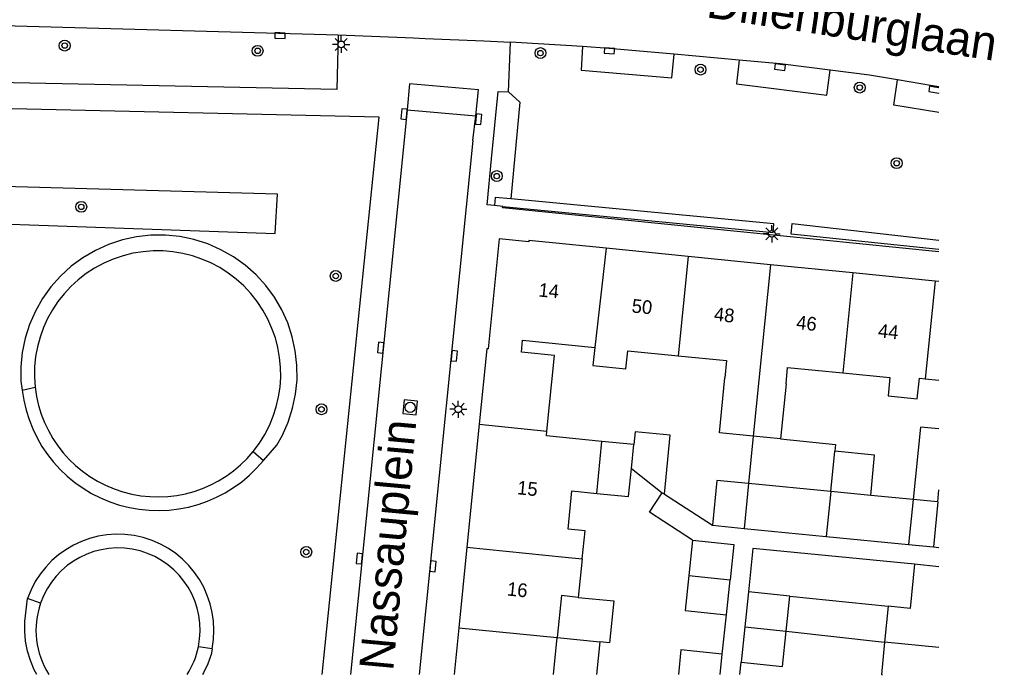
# Model space of a CAD drawing. Extents: x 132573 to 132944, y 398226 to 398676.
# Drawn here: x 132872.8 to 132944.2, y 398226.3 to 398274.2 of the extents above; entities that cross this region are included whole.
import ezdxf

# ---------------------------------------------------------------- set-up
doc = ezdxf.new("R2010")
doc.units = 0
for name, color, linetype in [('gg-afsc-erfafscheiding', 7, 'Continuous'), ('gg-anno-huisnummerreeks BGT', 7, 'Continuous'), ('gg-anno-openbare ruimte label', 7, 'Continuous'), ('gg-bbg-bijgebouw', 7, 'Continuous'), ('gg-bbg-gedigitaliseerde bebouwing', 7, 'Continuous'), ('gg-bbg-gedigitaliseerde bijgebouw', 7, 'Continuous'), ('gg-bbg-hoofdgebouw', 7, 'Continuous'), ('gg-bbg-luifel en loopbrug', 7, 'Continuous'), ('gg-bbg-tussenscheiding', 7, 'Continuous'), ('gg-knt-verharding', 7, 'Continuous'), ('gt-grn-groengrens', 7, 'Continuous'), ('gt-symb-boom', 7, 'Continuous'), ('gt-symb-kolk', 7, 'Continuous'), ('gt-symb-lichtmast', 7, 'Continuous'), ('gt-symb-rioolschacht', 7, 'Continuous')]:
    doc.layers.add(name, color=color, linetype=linetype)

msp = doc.modelspace()

# ---------------------------------------------------------------- linework, layer by layer
at = {"layer": 'gg-afsc-erfafscheiding'}
for p, q in [((132920.02, 398239.507), (132923.532, 398237.217)), ((132939.716, 398235.638), (132940.113, 398235.59)), ((132924.261, 398227.79), (132924.56, 398230.659)), ((132925.551, 398226.299), (132925.645, 398227.202))]:
    msp.add_line(p, q, dxfattribs=at)
for points in [[(132922.068, 398236.125), (132918.932, 398238.169), (132919.869, 398239.606)], [(132938.333, 398234.365), (132926.49, 398235.521), (132926.181, 398232.354)]]:
    msp.add_lwpolyline(points, dxfattribs=at)
at = {"layer": 'gg-bbg-bijgebouw'}
msp.add_line((132940.024, 398238.924), (132939.716, 398235.638), dxfattribs=at)
at = {"layer": 'gg-bbg-gedigitaliseerde bebouwing'}
for p, q in [((132911.426, 398244.114), (132911.98, 398249.64)), ((132933.08, 398248.376), (132936.533, 398248.038)), ((132928.922, 398247.568), (132928.515, 398243.538)), ((132938.682, 398247.991), (132939.12, 398247.945)), ((132939.12, 398247.945), (132940.113, 398247.842)), ((132928.515, 398243.538), (132926.529, 398243.732)), ((132914.005, 398234.769), (132913.72, 398231.945)), ((132940.113, 398234.188), (132938.333, 398234.365)), ((132936.404, 398231.29), (132936.142, 398228.67)), ((132911.908, 398226.299), (132912.178, 398228.999))]:
    msp.add_line(p, q, dxfattribs=at)
for points in [[(132909.551, 398249.885), (132909.637, 398250.761), (132914.92, 398250.241)], [(132914.92, 398250.241), (132914.791, 398248.918), (132917.207, 398248.682), (132917.335, 398249.993), (132921.04, 398249.631)], [(132921.04, 398249.631), (132924.572, 398249.286), (132924.447, 398248.005)], [(132928.922, 398247.568), (132929.04, 398248.772), (132933.08, 398248.376)], [(132926.529, 398243.732), (132924.054, 398243.974), (132924.447, 398248.005)], [(132936.533, 398248.038), (132936.394, 398246.7), (132938.525, 398246.478), (132938.682, 398247.991)], [(132915.45, 398243.355), (132911.391, 398243.762), (132911.426, 398244.114)], [(132912.973, 398236.938), (132913.252, 398239.73), (132915.069, 398239.548)], [(132914.005, 398234.769), (132914.211, 398236.813), (132912.973, 398236.938)], [(132938.333, 398234.365), (132938.009, 398231.13), (132936.404, 398231.29)], [(132913.72, 398231.945), (132912.485, 398232.069), (132912.178, 398228.999)], [(132936.142, 398228.67), (132935.907, 398226.307), (132935.99, 398226.299)]]:
    msp.add_lwpolyline(points, dxfattribs=at)
at = {"layer": 'gg-bbg-gedigitaliseerde bijgebouw'}
for p, q in [((132917.778, 398243.122), (132915.45, 398243.355)), ((132917.604, 398241.385), (132919.869, 398239.606)), ((132932.202, 398239.688), (132926.18, 398240.276)), ((132935.143, 398239.401), (132932.202, 398239.688)), ((132919.869, 398239.606), (132920.02, 398239.507)), ((132938.226, 398239.1), (132935.143, 398239.401)), ((132940.024, 398238.924), (132938.226, 398239.1)), ((132923.532, 398237.217), (132925.848, 398236.991)), ((132925.848, 398236.991), (132931.87, 398236.404)), ((132922.068, 398236.125), (132921.8, 398233.549)), ((132931.87, 398236.404), (132937.895, 398235.816)), ((132937.895, 398235.816), (132939.716, 398235.638)), ((132924.56, 398230.659), (132924.828, 398233.235)), ((132926.181, 398232.354), (132925.913, 398229.778)), ((132929.208, 398232.039), (132926.181, 398232.354)), ((132928.94, 398229.463), (132929.208, 398232.039)), ((132925.913, 398229.778), (132925.645, 398227.202))]:
    msp.add_line(p, q, dxfattribs=at)
for points in [[(132920.02, 398239.507), (132920.454, 398243.811), (132917.873, 398244.071), (132917.778, 398243.122)], [(132915.069, 398239.548), (132917.397, 398239.315), (132917.604, 398241.385)], [(132926.18, 398240.276), (132923.853, 398240.503), (132923.532, 398237.217)], [(132922.068, 398236.125), (132925.096, 398235.81), (132924.828, 398233.235)], [(132921.8, 398233.549), (132921.532, 398230.973), (132924.56, 398230.659)], [(132925.645, 398227.202), (132928.672, 398226.888), (132928.94, 398229.463)]]:
    msp.add_lwpolyline(points, dxfattribs=at)
at = {"layer": 'gg-bbg-hoofdgebouw'}
for p, q in [((132921.772, 398256.899), (132915.751, 398257.505)), ((132927.794, 398256.293), (132921.772, 398256.899)), ((132933.816, 398255.687), (132927.794, 398256.293)), ((132939.838, 398255.081), (132933.816, 398255.687)), ((132940.113, 398255.053), (132939.838, 398255.081)), ((132907.015, 398250.136), (132906.457, 398244.616)), ((132911.98, 398249.64), (132909.551, 398249.885)), ((132906.457, 398244.616), (132905.555, 398235.617)), ((132905.555, 398235.617), (132904.964, 398229.721)), ((132904.964, 398229.721), (132904.622, 398226.299))]:
    msp.add_line(p, q, dxfattribs=at)
for points in [[(132907.919, 398258.178), (132907.123, 398250.129), (132907.015, 398250.136)], [(132915.751, 398257.505), (132910.106, 398258.073), (132910.096, 398257.961), (132907.919, 398258.178)]]:
    msp.add_lwpolyline(points, dxfattribs=at)
at = {"layer": 'gg-bbg-luifel en loopbrug'}
for p, q in [((132926.529, 398243.732), (132926.18, 398240.276)), ((132932.202, 398239.688), (132932.501, 398242.646)), ((132940.024, 398238.924), (132940.113, 398239.806)), ((132929.208, 398232.039), (132936.404, 398231.29)), ((132912.178, 398228.999), (132915.284, 398228.688)), ((132928.94, 398229.463), (132936.142, 398228.67)), ((132915.284, 398228.688), (132915.045, 398226.299)), ((132924.106, 398226.299), (132924.261, 398227.79))]:
    msp.add_line(p, q, dxfattribs=at)
for points in [[(132940.113, 398244.276), (132938.762, 398244.408), (132938.226, 398239.1)], [(132928.515, 398243.538), (132932.551, 398243.144), (132932.501, 398242.646)], [(132935.143, 398239.401), (132935.392, 398242.359), (132932.501, 398242.646)], [(132913.72, 398231.945), (132916.317, 398231.685), (132916.01, 398228.616), (132915.284, 398228.688)], [(132924.261, 398227.79), (132921.233, 398228.093), (132921.046, 398226.299)]]:
    msp.add_lwpolyline(points, dxfattribs=at)
at = {"layer": 'gg-bbg-tussenscheiding'}
for p, q in [((132915.751, 398257.505), (132914.92, 398250.241)), ((132921.772, 398256.899), (132921.04, 398249.631)), ((132927.794, 398256.293), (132926.529, 398243.732)), ((132933.816, 398255.687), (132933.08, 398248.376)), ((132939.838, 398255.081), (132939.12, 398247.945)), ((132906.457, 398244.616), (132911.426, 398244.114)), ((132915.069, 398239.548), (132915.45, 398243.355)), ((132917.604, 398241.385), (132917.778, 398243.122)), ((132926.18, 398240.276), (132925.848, 398236.991)), ((132932.202, 398239.688), (132931.87, 398236.404)), ((132938.226, 398239.1), (132937.895, 398235.816)), ((132905.555, 398235.617), (132912.768, 398234.894)), ((132912.768, 398234.894), (132914.005, 398234.769)), ((132921.8, 398233.549), (132924.828, 398233.235)), ((132904.964, 398229.721), (132912.178, 398228.999)), ((132925.913, 398229.778), (132928.94, 398229.463)), ((132940.113, 398228.273), (132936.142, 398228.67))]:
    msp.add_line(p, q, dxfattribs=at)
at = {"layer": 'gg-knt-verharding'}
for p, q in [((132871.622, 398273.797), (132896.134, 398273.123)), ((132896.134, 398273.123), (132896.036, 398269.121)), ((132896.134, 398273.123), (132901.659, 398272.888)), ((132901.659, 398272.888), (132902.514, 398272.852)), ((132902.514, 398272.852), (132906.8, 398272.67)), ((132906.8, 398272.67), (132908.758, 398272.587)), ((132908.606, 398268.934), (132908.758, 398272.587)), ((132914.019, 398272.258), (132908.758, 398272.587)), ((132925.496, 398271.263), (132920.725, 398271.691)), ((132896.036, 398269.121), (132864.837, 398269.763)), ((132901.358, 398269.527), (132901.188, 398267.636)), ((132906.411, 398269.08), (132901.358, 398269.527)), ((132906.206, 398267.192), (132906.411, 398269.08)), ((132899.13, 398267.08), (132864.794, 398267.865)), ((132901.188, 398267.636), (132901.031, 398265.885)), ((132901.188, 398267.636), (132906.206, 398267.192)), ((132894.97, 398226.299), (132899.13, 398267.08)), ((132906.009, 398265.377), (132906.206, 398267.192)), ((132901.031, 398265.885), (132897.043, 398226.299)), ((132906.009, 398265.377), (132902.079, 398226.299)), ((132907.04, 398260.67), (132907.357, 398264.044)), ((132907.577, 398260.618), (132907.04, 398260.67)), ((132908.183, 398260.558), (132907.577, 398260.618)), ((132873.012, 398247.111), (132873.961, 398247.319)), ((132889.922, 398242.613), (132890.665, 398241.956)), ((132874.363, 398231.518), (132873.403, 398231.866)), ((132886.908, 398228.188), (132885.91, 398228.324))]:
    msp.add_line(p, q, dxfattribs=at)
for points in [[(132914.019, 398272.258), (132913.93, 398270.519), (132920.567, 398269.978), (132920.725, 398271.691)], [(132920.725, 398271.691), (132915.962, 398272.119), (132914.019, 398272.258)], [(132925.496, 398271.263), (132925.286, 398269.53), (132931.901, 398268.697), (132932.15, 398270.528)], [(132932.15, 398270.528), (132928.487, 398270.994), (132925.496, 398271.263)], [(132937.083, 398269.815), (132935.03, 398270.161), (132932.15, 398270.528)], [(132940.113, 398267.425), (132936.811, 398267.975), (132937.083, 398269.815)], [(132940.113, 398269.297), (132939.65, 398269.383), (132937.083, 398269.815)], [(132907.357, 398264.044), (132907.864, 398268.957), (132908.606, 398268.934)], [(132940.113, 398257.242), (132908.173, 398260.447), (132908.183, 398260.558)]]:
    msp.add_lwpolyline(points, dxfattribs=at)
for centre, radius, start, end in [((132882.922, 398248.293), 9.014, 320.94197, 186.20239), ((132882.936, 398248.293), 9.995, 186.79431, 320.64815), ((132882.933, 398248.329), 9.029, 186.42238, 320.72198), ((132880.025, 398229.547), 7.016, 348.83227, 160.69842), ((132880.036, 398229.556), 6.002, 348.15335, 160.92284), ((132880.027, 398229.526), 6.004, 160.62684, 212.51609), ((132880.027, 398229.526), 6.004, 327.48391, 348.44935)]:
    msp.add_arc(centre, radius, start, end, dxfattribs=at)
at = {"layer": 'gt-grn-groengrens'}
msp.add_line((132940.113, 398257.4), (132929.295, 398258.516), dxfattribs=at)
for points in [[(132908.606, 398268.934), (132909.439, 398268.187), (132908.787, 398261.111)], [(132854.2, 398262.504), (132854.161, 398259.901), (132891.539, 398258.578), (132891.698, 398261.456), (132854.2, 398262.504)], [(132908.787, 398261.111), (132907.636, 398261.22), (132907.577, 398260.618)], [(132908.183, 398260.558), (132927.971, 398258.653), (132928.037, 398259.294), (132908.787, 398261.111)], [(132929.295, 398258.516), (132929.378, 398259.318), (132940.113, 398258.087)], [(132890.665, 398241.956), (132891.663, 398243.085), (132892.062, 398243.806), (132892.487, 398244.776), (132892.809, 398245.785), (132893.023, 398246.822), (132893.128, 398247.876), (132893.122, 398248.935), (132893.005, 398249.988), (132892.779, 398251.023), (132892.446, 398252.028), (132892.009, 398252.993), (132891.474, 398253.908), (132890.847, 398254.761), (132890.133, 398255.544), (132889.342, 398256.248), (132888.482, 398256.866), (132887.561, 398257.39), (132886.591, 398257.815), (132885.582, 398258.137), (132884.545, 398258.351), (132883.491, 398258.456), (132882.432, 398258.449), (132881.379, 398258.333), (132880.344, 398258.106), (132879.339, 398257.773), (132878.374, 398257.337), (132877.459, 398256.802), (132876.606, 398256.174), (132875.823, 398255.461), (132875.119, 398254.67), (132874.501, 398253.81), (132873.977, 398252.889), (132873.552, 398251.919), (132873.23, 398250.91), (132873.016, 398249.873), (132872.911, 398248.819), (132872.918, 398247.759), (132873.012, 398247.111)], [(132874.084, 398226.299), (132873.893, 398226.645), (132873.609, 398227.316), (132873.397, 398228.013), (132873.259, 398228.728), (132873.197, 398229.453), (132873.211, 398230.182), (132873.403, 398231.866)], [(132886.908, 398228.188), (132886.835, 398227.758), (132886.597, 398227.069), (132886.288, 398226.41), (132886.221, 398226.299)]]:
    msp.add_lwpolyline(points, dxfattribs=at)
at = {"layer": 'gt-symb-boom'}
for centre, radius in [((132876.122, 398272.33), 0.4), ((132876.122, 398272.33), 0.2), ((132890.246, 398271.945), 0.4), ((132890.246, 398271.945), 0.2), ((132910.949, 398271.78), 0.4), ((132910.949, 398271.78), 0.2), ((132922.663, 398270.57), 0.4), ((132922.663, 398270.57), 0.2), ((132934.319, 398269.257), 0.4), ((132934.319, 398269.257), 0.2), ((132937.024, 398263.721), 0.4), ((132937.024, 398263.721), 0.2), ((132907.753, 398262.777), 0.4), ((132907.753, 398262.777), 0.2), ((132877.334, 398260.525), 0.4), ((132877.334, 398260.525), 0.2), ((132895.965, 398255.468), 0.4), ((132895.965, 398255.468), 0.2), ((132894.92, 398245.709), 0.4), ((132894.92, 398245.709), 0.2), ((132893.805, 398235.266), 0.4), ((132893.805, 398235.266), 0.2)]:
    msp.add_circle(centre, radius, dxfattribs=at)
at = {"layer": 'gt-symb-kolk'}
msp.add_line((132940.113, 398269.241), (132939.803, 398269.293), dxfattribs=at)
for points in [[(132891.888, 398273.257), (132891.513, 398273.267), (132891.503, 398272.867), (132892.252, 398272.847), (132892.263, 398273.247), (132891.888, 398273.257)], [(132916.007, 398272.14), (132915.633, 398272.168), (132915.603, 398271.769), (132916.351, 398271.713), (132916.381, 398272.112), (132916.007, 398272.14)], [(132928.505, 398270.94), (132928.133, 398270.987), (132928.083, 398270.59), (132928.827, 398270.496), (132928.877, 398270.893), (132928.505, 398270.94)], [(132939.803, 398269.293), (132939.433, 398269.355), (132939.367, 398268.96), (132940.107, 398268.837), (132940.113, 398268.874)], [(132901.161, 398267.296), (132901.196, 398267.669), (132900.798, 398267.707), (132900.728, 398266.96), (132901.126, 398266.923), (132901.161, 398267.296)], [(132906.223, 398266.959), (132906.183, 398266.586), (132906.581, 398266.544), (132906.661, 398267.289), (132906.263, 398267.332), (132906.223, 398266.959)], [(132899.448, 398250.197), (132899.485, 398250.57), (132899.088, 398250.61), (132899.013, 398249.864), (132899.411, 398249.824), (132899.448, 398250.197)], [(132904.438, 398249.635), (132904.401, 398249.262), (132904.798, 398249.222), (132904.873, 398249.968), (132904.475, 398250.008), (132904.438, 398249.635)], [(132897.892, 398234.765), (132897.929, 398235.138), (132897.532, 398235.178), (132897.457, 398234.432), (132897.855, 398234.392), (132897.892, 398234.765)], [(132902.883, 398234.233), (132902.846, 398233.86), (132903.243, 398233.82), (132903.318, 398234.566), (132902.92, 398234.606), (132902.883, 398234.233)]]:
    msp.add_lwpolyline(points, dxfattribs=at)
at = {"layer": 'gt-symb-lichtmast'}
for p, q in [((132896.184, 398272.59), (132895.919, 398272.855)), ((132896.361, 398272.663), (132896.361, 398273.038)), ((132896.538, 398272.59), (132896.803, 398272.855)), ((132896.111, 398272.413), (132895.736, 398272.413)), ((132896.184, 398272.236), (132895.919, 398271.971)), ((132896.361, 398272.163), (132896.361, 398271.788)), ((132896.803, 398271.971), (132896.538, 398272.236)), ((132896.611, 398272.413), (132896.986, 398272.413)), ((132927.704, 398258.727), (132927.439, 398258.992)), ((132927.881, 398258.8), (132927.881, 398259.175)), ((132928.058, 398258.727), (132928.323, 398258.992)), ((132927.631, 398258.55), (132927.256, 398258.55)), ((132927.704, 398258.373), (132927.439, 398258.108)), ((132927.881, 398258.3), (132927.881, 398257.925)), ((132928.323, 398258.108), (132928.058, 398258.373)), ((132928.131, 398258.55), (132928.506, 398258.55)), ((132904.756, 398245.89), (132904.491, 398246.155)), ((132904.933, 398245.963), (132904.933, 398246.338)), ((132905.11, 398245.89), (132905.375, 398246.155)), ((132904.683, 398245.713), (132904.308, 398245.713)), ((132904.756, 398245.536), (132904.491, 398245.271)), ((132904.933, 398245.463), (132904.933, 398245.088)), ((132905.375, 398245.271), (132905.11, 398245.536)), ((132905.183, 398245.713), (132905.558, 398245.713))]:
    msp.add_line(p, q, dxfattribs=at)
for centre in [(132896.361, 398272.413), (132927.881, 398258.55), (132904.933, 398245.713)]:
    msp.add_circle(centre, 0.25, dxfattribs=at)
at = {"layer": 'gt-symb-rioolschacht'}
msp.add_lwpolyline([(132901.86, 398245.302), (132901.96, 398246.296), (132900.966, 398246.396), (132900.866, 398245.402)], close=True, dxfattribs=at)
msp.add_circle((132901.413, 398245.849), 0.375, dxfattribs=at)

# ---------------------------------------------------------------- texts
at = {"layer": 'gg-anno-huisnummerreeks BGT'}
for s, rotation, p in [('14', 354.4, (132910.776, 398253.967)), ('50', 354.3, (132917.596, 398252.797)), ('48', 354.3, (132923.616, 398252.191)), ('46', 354.3, (132929.638, 398251.585)), ('44', 354.3, (132935.627, 398250.982)), ('15', 354.3, (132909.211, 398239.493)), ('16', 354.3, (132908.472, 398232.082))]:
    msp.add_text(s, height=1, rotation=rotation, dxfattribs=at).set_placement(p)
at = {"layer": 'gg-anno-openbare ruimte label'}
for s, rotation, p in [('Dillenburglaan', 351.4, (132923.02, 398274.411)), ('Nassauplein', 84.7, (132900.163, 398226.513))]:
    msp.add_text(s, height=2.5, rotation=rotation, dxfattribs=at).set_placement(p)

doc.saveas('drawing.dxf')
